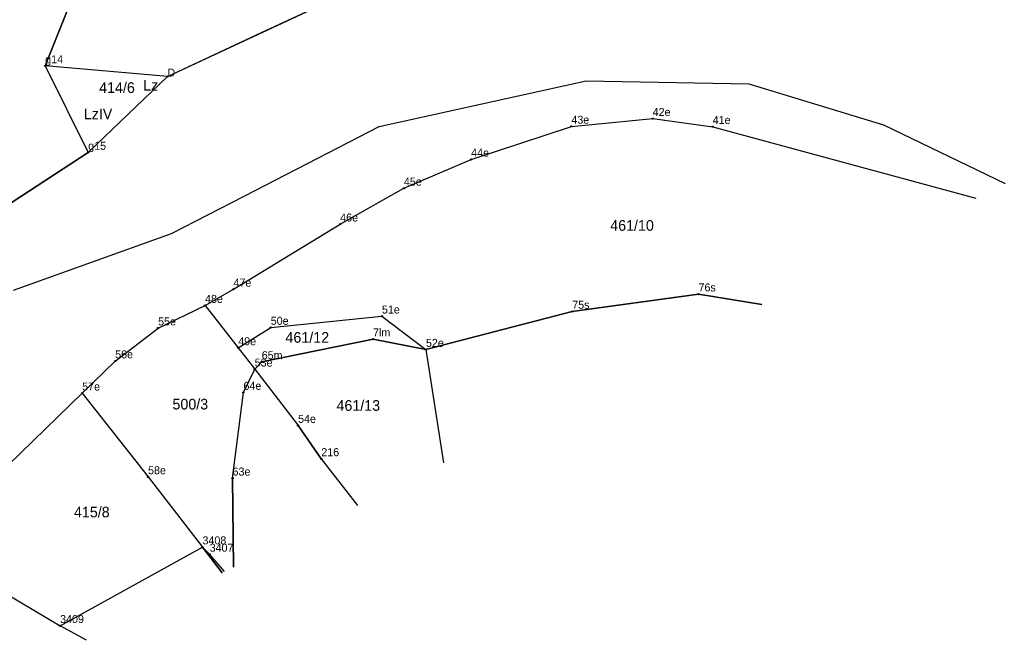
# Model space of a CAD drawing. Extents: x 7467189 to 7469366, y 5491487 to 5492734.
# Drawn here: x 7469153.7 to 7469292.3, y 5491547.5 to 5491634.8 of the extents above; entities that cross this region are included whole.
import ezdxf

# ---------------------------------------------------------------- set-up
doc = ezdxf.new("R2010")
doc.units = 0
for name, color, linetype in [('203-punkt graniczny', 7, 'Continuous'), ('203-punkt graniczny-Atr103', 7, 'Continuous'), ('209-oznaczenie konturu klasyfikacyjnego', 7, 'Continuous'), ('210-oznaczenie konturu użytku gruntowego', 7, 'Continuous'), ('211-numer działki ewidencyjnej', 7, 'Continuous'), ('217-kontur klasyfikacyjny', 7, 'Continuous'), ('218-kontur użytku gruntowego', 7, 'Continuous'), ('219-działka ewidencyjna', 7, 'Continuous')]:
    doc.layers.add(name, color=color, linetype=linetype)

# ---------------------------------------------------------------- blocks, each defined once
blk = doc.blocks.new('203')
blk.add_circle((0, 0), 0.09)

msp = doc.modelspace()

# ---------------------------------------------------------------- linework, layer by layer
at = {"layer": '217-kontur klasyfikacyjny'}
for points in [[(7469174.5, 5491626.84), (7469212.78, 5491644.72)], [(7469161.59, 5491639.19), (7469157.31, 5491628.34)], [(7469157.31, 5491628.34), (7469163.35, 5491616.17)], [(7469163.35, 5491616.17), (7469174.5, 5491626.84)], [(7469249.17, 5491596.23), (7469231.41, 5491593.79)], [(7469258.05, 5491594.76), (7469249.17, 5491596.23)], [(7469231.41, 5491593.79), (7469210.84, 5491588.43)], [(7469203.4, 5491589.89), (7469187.75, 5491586.69)], [(7469210.84, 5491588.43), (7469203.4, 5491589.89)], [(7469187.75, 5491586.69), (7469186.76, 5491585.66)], [(7469186.76, 5491585.66), (7469192.86, 5491577.74)], [(7469192.86, 5491577.74), (7469196.13, 5491573.06)], [(7469196.13, 5491573.06), (7469201.23, 5491566.49)], [(7469180.43, 5491559.61), (7469179.42, 5491560.64)], [(7469179.42, 5491560.64), (7469182.2, 5491557.02)], [(7469182.53, 5491557.19), (7469180.43, 5491559.61)]]:
    msp.add_lwpolyline(points, dxfattribs=at)
at = {"layer": '218-kontur użytku gruntowego'}
for points in [[(7469161.59, 5491639.19), (7469157.31, 5491628.34)], [(7469187.74, 5491633.03), (7469200.3, 5491638.89)], [(7469174.5, 5491626.84), (7469187.74, 5491633.03)], [(7469157.31, 5491628.34), (7469163.35, 5491616.17)], [(7469163.35, 5491616.17), (7469174.5, 5491626.84)], [(7469204.27, 5491619.83), (7469233.35, 5491626.22)], [(7469233.35, 5491626.22), (7469256.24, 5491625.82)], [(7469256.24, 5491625.82), (7469275.17, 5491620.07)], [(7469198.53, 5491616.86), (7469204.27, 5491619.83)], [(7469275.17, 5491620.07), (7469292.3, 5491611.81)], [(7469185.26, 5491610.01), (7469198.53, 5491616.86)], [(7469163.35, 5491616.17), (7469145.42, 5491604.47)], [(7469175.05, 5491604.74), (7469185.26, 5491610.01)], [(7469152.87, 5491596.77), (7469175.05, 5491604.74)], [(7469231.41, 5491593.79), (7469249.17, 5491596.23)], [(7469249.17, 5491596.23), (7469258.05, 5491594.76)], [(7469210.84, 5491588.43), (7469231.41, 5491593.79)], [(7469187.75, 5491586.69), (7469203.4, 5491589.89)], [(7469203.4, 5491589.89), (7469210.84, 5491588.43)], [(7469186.76, 5491585.66), (7469187.75, 5491586.69)], [(7469185.18, 5491582.39), (7469186.76, 5491585.66)], [(7469186.76, 5491585.66), (7469192.86, 5491577.74)], [(7469183.65, 5491570.32), (7469185.18, 5491582.39)], [(7469192.86, 5491577.74), (7469196.13, 5491573.06)], [(7469196.13, 5491573.06), (7469201.23, 5491566.49)], [(7469183.8, 5491557.82), (7469183.65, 5491570.32)], [(7469180.43, 5491559.61), (7469179.42, 5491560.64)], [(7469179.42, 5491560.64), (7469182.2, 5491557.02)], [(7469182.53, 5491557.19), (7469180.43, 5491559.61)]]:
    msp.add_lwpolyline(points, dxfattribs=at)
at = {"layer": '219-działka ewidencyjna'}
for points in [[(7469174.5, 5491626.84), (7469212.78, 5491644.72)], [(7469157.31, 5491628.34), (7469161.59, 5491639.19)], [(7469174.5, 5491626.84), (7469157.31, 5491628.34)], [(7469157.31, 5491628.34), (7469163.35, 5491616.17)], [(7469174.5, 5491626.84), (7469163.35, 5491616.17)], [(7469231.29, 5491619.84), (7469242.72, 5491620.92)], [(7469242.72, 5491620.92), (7469251.16, 5491619.79)], [(7469217.2, 5491615.19), (7469231.29, 5491619.84)], [(7469251.16, 5491619.79), (7469288.14, 5491609.74)], [(7469145.42, 5491604.47), (7469163.35, 5491616.17)], [(7469207.74, 5491611.12), (7469217.2, 5491615.19)], [(7469198.78, 5491606.07), (7469207.74, 5491611.12)], [(7469183.78, 5491596.92), (7469198.78, 5491606.07)], [(7469179.78, 5491594.63), (7469183.78, 5491596.92)], [(7469231.41, 5491593.79), (7469249.17, 5491596.23)], [(7469249.17, 5491596.23), (7469258.05, 5491594.76)], [(7469173.18, 5491591.45), (7469179.78, 5491594.63)], [(7469179.78, 5491594.63), (7469184.45, 5491588.66)], [(7469210.84, 5491588.43), (7469231.41, 5491593.79)], [(7469189.02, 5491591.54), (7469204.65, 5491593.12)], [(7469204.65, 5491593.12), (7469210.84, 5491588.43)], [(7469167.14, 5491586.82), (7469173.18, 5491591.45)], [(7469184.45, 5491588.66), (7469189.02, 5491591.54)], [(7469187.75, 5491586.69), (7469203.4, 5491589.89)], [(7469203.4, 5491589.89), (7469210.84, 5491588.43)], [(7469184.45, 5491588.66), (7469186.76, 5491585.66)], [(7469210.84, 5491588.43), (7469213.29, 5491572.49)], [(7469167.14, 5491586.82), (7469162.5, 5491582.3)], [(7469186.76, 5491585.66), (7469187.75, 5491586.69)], [(7469185.18, 5491582.39), (7469186.76, 5491585.66)], [(7469186.76, 5491585.66), (7469192.86, 5491577.74)], [(7469150.41, 5491570.55), (7469162.5, 5491582.3)], [(7469162.5, 5491582.3), (7469171.77, 5491570.51)], [(7469183.65, 5491570.32), (7469185.18, 5491582.39)], [(7469196.13, 5491573.06), (7469192.86, 5491577.74)], [(7469196.13, 5491573.06), (7469201.23, 5491566.49)], [(7469171.77, 5491570.51), (7469179.42, 5491560.64)], [(7469183.65, 5491570.32), (7469183.8, 5491557.82)], [(7469159.4, 5491549.57), (7469179.42, 5491560.64)], [(7469179.42, 5491560.64), (7469180.43, 5491559.61)], [(7469182.2, 5491557.02), (7469179.42, 5491560.64)], [(7469144.1, 5491558.64), (7469159.4, 5491549.57)], [(7469182.53, 5491557.19), (7469180.43, 5491559.61)], [(7469163.11, 5491547.52), (7469159.4, 5491549.57)]]:
    msp.add_lwpolyline(points, dxfattribs=at)

# ---------------------------------------------------------------- block references
at = {"layer": '203-punkt graniczny'}
for p in [(7469157.31, 5491628.34), (7469174.5, 5491626.84), (7469242.72, 5491620.92), (7469231.29, 5491619.84), (7469251.16, 5491619.79), (7469163.35, 5491616.17), (7469217.2, 5491615.19), (7469207.74, 5491611.12), (7469198.78, 5491606.07), (7469183.78, 5491596.92), (7469249.17, 5491596.23), (7469179.78, 5491594.63), (7469204.65, 5491593.12), (7469231.41, 5491593.79), (7469173.18, 5491591.45), (7469189.02, 5491591.54), (7469203.4, 5491589.89), (7469184.45, 5491588.66), (7469210.84, 5491588.43), (7469167.14, 5491586.82), (7469187.75, 5491586.69), (7469186.76, 5491585.66), (7469162.5, 5491582.3), (7469185.18, 5491582.39), (7469192.86, 5491577.74), (7469196.13, 5491573.06), (7469171.77, 5491570.51), (7469183.65, 5491570.32), (7469179.42, 5491560.64), (7469180.43, 5491559.61), (7469159.4, 5491549.57)]:
    msp.add_blockref('203', p, dxfattribs=at)

# ---------------------------------------------------------------- texts
at = {"layer": '203-punkt graniczny-Atr103'}
for s, height, p in [('g14', 1.125, (7469157.31, 5491628.71)), ('D', 1.12, (7469174.5, 5491626.84)), ('42e', 1.125, (7469242.72, 5491621.29)), ('43e', 1.125, (7469231.29, 5491620.21)), ('41e', 1.125, (7469251.16, 5491620.17)), ('g15', 1.125, (7469163.35, 5491616.54)), ('44e', 1.125, (7469217.2, 5491615.57)), ('45e', 1.125, (7469207.74, 5491611.5)), ('46e', 1.125, (7469198.78, 5491606.45)), ('47e', 1.125, (7469183.78, 5491597.29)), ('76s', 1.125, (7469249.17, 5491596.61)), ('48e', 1.125, (7469179.78, 5491595)), ('51e', 1.125, (7469204.65, 5491593.5)), ('75s', 1.125, (7469231.41, 5491594.17)), ('55e', 1.125, (7469173.18, 5491591.83)), ('50e', 1.125, (7469189.02, 5491591.92)), ('7lm', 1.125, (7469203.4, 5491590.27)), ('49e', 1.125, (7469184.45, 5491589.04)), ('52e', 1.125, (7469210.84, 5491588.81)), ('56e', 1.125, (7469167.14, 5491587.2)), ('65m', 1.125, (7469187.75, 5491587.07)), ('53e', 1.125, (7469186.76, 5491586.04)), ('57e', 1.125, (7469162.5, 5491582.67)), ('64e', 1.125, (7469185.18, 5491582.77)), ('54e', 1.125, (7469192.86, 5491578.12)), ('216', 1.125, (7469196.13, 5491573.43)), ('58e', 1.125, (7469171.77, 5491570.89)), ('63e', 1.125, (7469183.65, 5491570.7)), ('3408', 1.125, (7469179.42, 5491561.02)), ('3407', 1.125, (7469180.43, 5491559.99)), ('3409', 1.125, (7469159.4, 5491549.95))]:
    msp.add_text(s, height=height, dxfattribs=at).set_placement(p)
at = {"layer": '209-oznaczenie konturu klasyfikacyjnego'}
msp.add_text('LzIV', height=1.5, dxfattribs=at).set_placement((7469162.73, 5491620.84))
at = {"layer": '210-oznaczenie konturu użytku gruntowego'}
msp.add_text('Lz', height=1.5, dxfattribs=at).set_placement((7469171.07, 5491624.87))
at = {"layer": '211-numer działki ewidencyjnej'}
for s, p in [('414/6', (7469164.89, 5491624.54)), ('461/10', (7469236.75, 5491605.15)), ('461/12', (7469191.09, 5491589.39)), ('500/3', (7469175.2, 5491580)), ('461/13', (7469198.26, 5491579.81)), ('415/8', (7469161.35, 5491564.82))]:
    msp.add_text(s, height=1.5, dxfattribs=at).set_placement(p)

doc.saveas('drawing.dxf')
